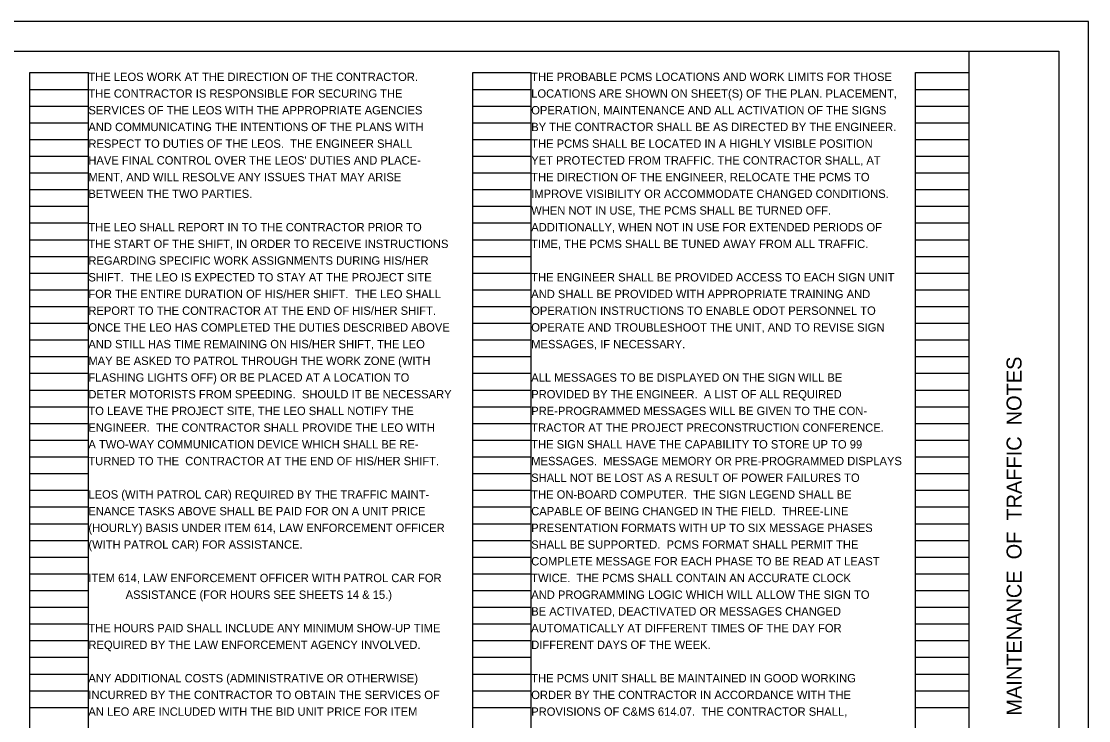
# Model space of a CAD drawing. Extents: x -7.9 to 34, y 0 to 22.
# Drawn here: x 16.12 to 34, y 10.28 to 22 of the extents above; entities that cross this region are included whole.
import ezdxf

# ---------------------------------------------------------------- set-up
doc = ezdxf.new("R2010")
doc.units = 0
for name, color, linetype in [('SH_Border', 7, 'Continuous'), ('SH_Cut_Line', 7, 'Continuous'), ('SH_Data', 7, 'Continuous'), ('SH_Text', 7, 'Continuous')]:
    doc.layers.add(name, color=color, linetype=linetype)

msp = doc.modelspace()

# ---------------------------------------------------------------- linework, layer by layer
at = {"layer": 'SH_Border'}
msp.add_line((32, 0.5), (32, 21.5), dxfattribs=at)
msp.add_lwpolyline([(1.5, 21.5), (33.5, 21.5), (33.5, 0.5), (1.5, 0.5)], close=True, dxfattribs=at)
at = {"layer": 'SH_Cut_Line'}
msp.add_lwpolyline([(0, 0), (34, 0), (34, 22), (0, 22)], close=True, dxfattribs=at)
at = {"layer": 'SH_Data'}
for p, q in [((16.26, 0.98), (16.26, 21.14)), ((16.26, 21.14), (17.24, 21.14)), ((17.24, 0.98), (17.24, 21.14)), ((23.68, 0.98), (23.68, 21.14)), ((23.68, 21.14), (24.66, 21.14)), ((24.66, 0.98), (24.66, 21.14)), ((31.1, 0.98), (31.1, 21.14)), ((31.1, 21.14), (32, 21.14)), ((32, 0.98), (32, 21.14)), ((16.26, 20.86), (17.24, 20.86)), ((23.68, 20.86), (24.66, 20.86)), ((31.1, 20.86), (32, 20.86)), ((16.26, 20.58), (17.24, 20.58)), ((23.68, 20.58), (24.66, 20.58)), ((31.1, 20.58), (32, 20.58)), ((16.26, 20.3), (17.24, 20.3)), ((23.68, 20.3), (24.66, 20.3)), ((31.1, 20.3), (32, 20.3)), ((16.26, 20.02), (17.24, 20.02)), ((23.68, 20.02), (24.66, 20.02)), ((31.1, 20.02), (32, 20.02)), ((16.26, 19.74), (17.24, 19.74)), ((23.68, 19.74), (24.66, 19.74)), ((31.1, 19.74), (32, 19.74)), ((16.26, 19.46), (17.24, 19.46)), ((23.68, 19.46), (24.66, 19.46)), ((31.1, 19.46), (32, 19.46)), ((16.26, 19.18), (17.24, 19.18)), ((23.68, 19.18), (24.66, 19.18)), ((31.1, 19.18), (32, 19.18)), ((16.26, 18.9), (17.24, 18.9)), ((23.68, 18.9), (24.66, 18.9)), ((31.1, 18.9), (32, 18.9)), ((16.26, 18.62), (17.24, 18.62)), ((23.68, 18.62), (24.66, 18.62)), ((31.1, 18.62), (32, 18.62)), ((16.26, 18.34), (17.24, 18.34)), ((23.68, 18.34), (24.66, 18.34)), ((31.1, 18.34), (32, 18.34)), ((16.26, 18.06), (17.24, 18.06)), ((23.68, 18.06), (24.66, 18.06)), ((31.1, 18.06), (32, 18.06)), ((16.26, 17.78), (17.24, 17.78)), ((23.68, 17.78), (24.66, 17.78)), ((31.1, 17.78), (32, 17.78)), ((16.26, 17.5), (17.24, 17.5)), ((23.68, 17.5), (24.66, 17.5)), ((31.1, 17.5), (32, 17.5)), ((16.26, 17.22), (17.24, 17.22)), ((23.68, 17.22), (24.66, 17.22)), ((31.1, 17.22), (32, 17.22)), ((16.26, 16.94), (17.24, 16.94)), ((23.68, 16.94), (24.66, 16.94)), ((31.1, 16.94), (32, 16.94)), ((16.26, 16.66), (17.24, 16.66)), ((23.68, 16.66), (24.66, 16.66)), ((31.1, 16.66), (32, 16.66)), ((16.26, 16.38), (17.24, 16.38)), ((23.68, 16.38), (24.66, 16.38)), ((31.1, 16.38), (32, 16.38)), ((16.26, 16.1), (17.24, 16.1)), ((23.68, 16.1), (24.66, 16.1)), ((31.1, 16.1), (32, 16.1)), ((16.26, 15.82), (17.24, 15.82)), ((23.68, 15.82), (24.66, 15.82)), ((31.1, 15.82), (32, 15.82)), ((16.26, 15.54), (17.24, 15.54)), ((23.68, 15.54), (24.66, 15.54)), ((31.1, 15.54), (32, 15.54)), ((16.26, 15.26), (17.24, 15.26)), ((23.68, 15.26), (24.66, 15.26)), ((31.1, 15.26), (32, 15.26)), ((16.26, 14.98), (17.24, 14.98)), ((23.68, 14.98), (24.66, 14.98)), ((31.1, 14.98), (32, 14.98)), ((16.26, 14.7), (17.24, 14.7)), ((23.68, 14.7), (24.66, 14.7)), ((31.1, 14.7), (32, 14.7)), ((16.26, 14.42), (17.24, 14.42)), ((23.68, 14.42), (24.66, 14.42)), ((31.1, 14.42), (32, 14.42)), ((16.26, 14.14), (17.24, 14.14)), ((23.68, 14.14), (24.66, 14.14)), ((31.1, 14.14), (32, 14.14)), ((16.26, 13.86), (17.24, 13.86)), ((23.68, 13.86), (24.66, 13.86)), ((31.1, 13.86), (32, 13.86)), ((16.26, 13.58), (17.24, 13.58)), ((23.68, 13.58), (24.66, 13.58)), ((31.1, 13.58), (32, 13.58)), ((16.26, 13.3), (17.24, 13.3)), ((23.68, 13.3), (24.66, 13.3)), ((31.1, 13.3), (32, 13.3)), ((16.26, 13.02), (17.24, 13.02)), ((23.68, 13.02), (24.66, 13.02)), ((31.1, 13.02), (32, 13.02)), ((16.26, 12.74), (17.24, 12.74)), ((23.68, 12.74), (24.66, 12.74)), ((31.1, 12.74), (32, 12.74)), ((16.26, 12.46), (17.24, 12.46)), ((23.68, 12.46), (24.66, 12.46)), ((31.1, 12.46), (32, 12.46)), ((16.26, 12.18), (17.24, 12.18)), ((23.68, 12.18), (24.66, 12.18)), ((31.1, 12.18), (32, 12.18)), ((16.26, 11.9), (17.24, 11.9)), ((23.68, 11.9), (24.66, 11.9)), ((31.1, 11.9), (32, 11.9)), ((16.26, 11.62), (17.24, 11.62)), ((23.68, 11.62), (24.66, 11.62)), ((31.1, 11.62), (32, 11.62)), ((16.26, 11.34), (17.24, 11.34)), ((23.68, 11.34), (24.66, 11.34)), ((31.1, 11.34), (32, 11.34)), ((16.26, 11.06), (17.24, 11.06)), ((23.68, 11.06), (24.66, 11.06)), ((31.1, 11.06), (32, 11.06)), ((16.26, 10.78), (17.24, 10.78)), ((23.68, 10.78), (24.66, 10.78)), ((31.1, 10.78), (32, 10.78)), ((16.26, 10.5), (17.24, 10.5)), ((23.68, 10.5), (24.66, 10.5)), ((31.1, 10.5), (32, 10.5))]:
    msp.add_line(p, q, dxfattribs=at)

# ---------------------------------------------------------------- texts
msp.add_text('MAINTENANCE  OF  TRAFFIC  NOTES', height=0.25, rotation=90, dxfattribs=at).set_placement((32.875, 10.363))
at = {"layer": 'SH_Text'}
for s, p in [('THE LEOS WORK AT THE DIRECTION OF THE CONTRACTOR.', (17.24, 21)), ('THE PROBABLE PCMS LOCATIONS AND WORK LIMITS FOR THOSE', (24.66, 21)), ('THE CONTRACTOR IS RESPONSIBLE FOR SECURING THE', (17.24, 20.72)), ('LOCATIONS ARE SHOWN ON SHEET(S) OF THE PLAN. PLACEMENT,', (24.66, 20.72)), ('SERVICES OF THE LEOS WITH THE APPROPRIATE AGENCIES', (17.24, 20.44)), ('OPERATION, MAINTENANCE AND ALL ACTIVATION OF THE SIGNS', (24.66, 20.44)), ('AND COMMUNICATING THE INTENTIONS OF THE PLANS WITH', (17.24, 20.16)), ('BY THE CONTRACTOR SHALL BE AS DIRECTED BY THE ENGINEER.', (24.66, 20.16)), ('RESPECT TO DUTIES OF THE LEOS.  THE ENGINEER SHALL', (17.24, 19.88)), ('THE PCMS SHALL BE LOCATED IN A HIGHLY VISIBLE POSITION', (24.66, 19.88)), ("HAVE FINAL CONTROL OVER THE LEOS' DUTIES AND PLACE-", (17.24, 19.6)), ('YET PROTECTED FROM TRAFFIC. THE CONTRACTOR SHALL, AT ', (24.66, 19.6)), ('MENT, AND WILL RESOLVE ANY ISSUES THAT MAY ARISE', (17.24, 19.32)), ('THE DIRECTION OF THE ENGINEER, RELOCATE THE PCMS TO ', (24.66, 19.32)), ('BETWEEN THE TWO PARTIES.', (17.24, 19.04)), ('IMPROVE VISIBILITY OR ACCOMMODATE CHANGED CONDITIONS. ', (24.66, 19.04)), ('WHEN NOT IN USE, THE PCMS SHALL BE TURNED OFF. ', (24.66, 18.76)), ('THE LEO SHALL REPORT IN TO THE CONTRACTOR PRIOR TO', (17.24, 18.48)), ('ADDITIONALLY, WHEN NOT IN USE FOR EXTENDED PERIODS OF', (24.66, 18.48)), ('THE START OF THE SHIFT, IN ORDER TO RECEIVE INSTRUCTIONS', (17.24, 18.2)), ('TIME, THE PCMS SHALL BE TUNED AWAY FROM ALL TRAFFIC.', (24.66, 18.2)), ('REGARDING SPECIFIC WORK ASSIGNMENTS DURING HIS/HER', (17.24, 17.92)), ('SHIFT.  THE LEO IS EXPECTED TO STAY AT THE PROJECT SITE', (17.24, 17.64)), ('THE ENGINEER SHALL BE PROVIDED ACCESS TO EACH SIGN UNIT', (24.66, 17.64)), ('FOR THE ENTIRE DURATION OF HIS/HER SHIFT.  THE LEO SHALL', (17.24, 17.36)), ('AND SHALL BE PROVIDED WITH APPROPRIATE TRAINING AND', (24.66, 17.36)), ('REPORT TO THE CONTRACTOR AT THE END OF HIS/HER SHIFT.', (17.24, 17.08)), ('OPERATION INSTRUCTIONS TO ENABLE ODOT PERSONNEL TO', (24.66, 17.08)), ('ONCE THE LEO HAS COMPLETED THE DUTIES DESCRIBED ABOVE', (17.24, 16.8)), ('OPERATE AND TROUBLESHOOT THE UNIT, AND TO REVISE SIGN', (24.66, 16.8)), ('AND STILL HAS TIME REMAINING ON HIS/HER SHIFT, THE LEO', (17.24, 16.52)), ('MESSAGES, IF NECESSARY.', (24.66, 16.52)), ('MAY BE ASKED TO PATROL THROUGH THE WORK ZONE (WITH', (17.24, 16.24)), ('FLASHING LIGHTS OFF) OR BE PLACED AT A LOCATION TO', (17.24, 15.96)), ('ALL MESSAGES TO BE DISPLAYED ON THE SIGN WILL BE', (24.66, 15.96)), ('DETER MOTORISTS FROM SPEEDING.  SHOULD IT BE NECESSARY', (17.24, 15.68)), ('PROVIDED BY THE ENGINEER.  A LIST OF ALL REQUIRED', (24.66, 15.68)), ('TO LEAVE THE PROJECT SITE, THE LEO SHALL NOTIFY THE', (17.24, 15.4)), ('PRE-PROGRAMMED MESSAGES WILL BE GIVEN TO THE CON-', (24.66, 15.4)), ('ENGINEER.  THE CONTRACTOR SHALL PROVIDE THE LEO WITH', (17.24, 15.12)), ('TRACTOR AT THE PROJECT PRECONSTRUCTION CONFERENCE.', (24.66, 15.12)), ('A TWO-WAY COMMUNICATION DEVICE WHICH SHALL BE RE-', (17.24, 14.84)), ('THE SIGN SHALL HAVE THE CAPABILITY TO STORE UP TO 99', (24.66, 14.84)), ('TURNED TO THE  CONTRACTOR AT THE END OF HIS/HER SHIFT.', (17.24, 14.56)), ('MESSAGES.  MESSAGE MEMORY OR PRE-PROGRAMMED DISPLAYS', (24.66, 14.56)), ('SHALL NOT BE LOST AS A RESULT OF POWER FAILURES TO', (24.66, 14.28)), ('LEOS (WITH PATROL CAR) REQUIRED BY THE TRAFFIC MAINT-', (17.24, 14)), ('THE ON-BOARD COMPUTER.  THE SIGN LEGEND SHALL BE', (24.66, 14)), ('ENANCE TASKS ABOVE SHALL BE PAID FOR ON A UNIT PRICE', (17.24, 13.72)), ('CAPABLE OF BEING CHANGED IN THE FIELD.  THREE-LINE', (24.66, 13.72)), ('(HOURLY) BASIS UNDER ITEM 614, LAW ENFORCEMENT OFFICER', (17.24, 13.44)), ('PRESENTATION FORMATS WITH UP TO SIX MESSAGE PHASES', (24.66, 13.44)), ('(WITH PATROL CAR) FOR ASSISTANCE.', (17.24, 13.16)), ('SHALL BE SUPPORTED.  PCMS FORMAT SHALL PERMIT THE', (24.66, 13.16)), ('COMPLETE MESSAGE FOR EACH PHASE TO BE READ AT LEAST', (24.66, 12.88)), ('ITEM 614, LAW ENFORCEMENT OFFICER WITH PATROL CAR FOR', (17.24, 12.6)), ('TWICE.  THE PCMS SHALL CONTAIN AN ACCURATE CLOCK', (24.66, 12.6)), ('            ASSISTANCE (FOR HOURS SEE SHEETS 14 & 15.)', (17.24, 12.32)), ('AND PROGRAMMING LOGIC WHICH WILL ALLOW THE SIGN TO', (24.66, 12.32)), ('BE ACTIVATED, DEACTIVATED OR MESSAGES CHANGED', (24.66, 12.04)), ('THE HOURS PAID SHALL INCLUDE ANY MINIMUM SHOW-UP TIME', (17.24, 11.76)), ('AUTOMATICALLY AT DIFFERENT TIMES OF THE DAY FOR', (24.66, 11.76)), ('REQUIRED BY THE LAW ENFORCEMENT AGENCY INVOLVED.', (17.24, 11.48)), ('DIFFERENT DAYS OF THE WEEK.', (24.66, 11.48)), ('ANY ADDITIONAL COSTS (ADMINISTRATIVE OR OTHERWISE)', (17.24, 10.92)), ('THE PCMS UNIT SHALL BE MAINTAINED IN GOOD WORKING', (24.66, 10.92)), ('INCURRED BY THE CONTRACTOR TO OBTAIN THE SERVICES OF', (17.24, 10.64)), ('ORDER BY THE CONTRACTOR IN ACCORDANCE WITH THE', (24.66, 10.64)), ('AN LEO ARE INCLUDED WITH THE BID UNIT PRICE FOR ITEM', (17.24, 10.36)), ('PROVISIONS OF C&MS 614.07.  THE CONTRACTOR SHALL, ', (24.66, 10.36))]:
    msp.add_text(s, height=0.14, dxfattribs=at).set_placement(p)

doc.saveas('drawing.dxf')
